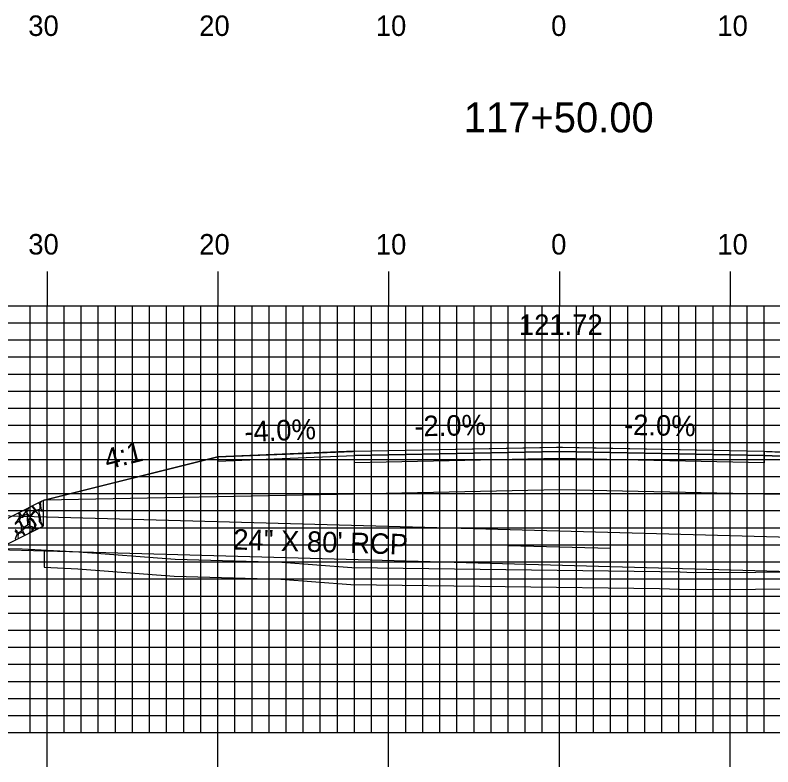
# Model space of a CAD drawing. Extents: x 1771235 to 1771579, y 442591 to 442811.
# Drawn here: x 1771369.2 to 1771413.57, y 442696.66 to 442740.68 of the extents above; entities that cross this region are included whole.
import ezdxf

# ---------------------------------------------------------------- set-up
doc = ezdxf.new("R2010")
doc.units = 0
for name, color, linetype in [('ANNOTATION', 7, 'Continuous'), ('D_Drainage_Culvert', 7, 'Continuous'), ('D_Drainage_Text', 7, 'Continuous'), ('D_Roadway_Centerline', 7, 'Continuous'), ('D_Roadway_Centerline_Text', 7, 'Continuous'), ('D_Roadway_Edge_Shoulder', 7, 'Continuous'), ('D_Roadway_Edge_TW', 7, 'Continuous'), ('D_Roadway_Pavement', 7, 'Continuous'), ('D_Roadway_SlopeLines', 7, 'Continuous'), ('D_Roadway_SubGrade', 7, 'Continuous'), ('GRUBBING IN FILL', 7, 'Continuous'), ('H_V ANNOTATION', 7, 'Continuous'), ('MAJOR', 7, 'Continuous'), ('MINOR', 7, 'Continuous'), ('S_Roadway_Centerline', 7, 'Continuous')]:
    doc.layers.add(name, color=color, linetype=linetype)

msp = doc.modelspace()

# ---------------------------------------------------------------- linework, layer by layer
at = {"layer": 'ANNOTATION'}
msp.add_line((1771365.236, 442709.463), (1771370.82, 442712.255), dxfattribs=at)
at = {"layer": 'D_Drainage_Culvert'}
for p, q in [((1771365.291, 442711.463), (1771445.349, 442709.255)), ((1771398.067, 442709.629), (1771404.067, 442709.463)), ((1771365.236, 442709.463), (1771445.294, 442707.255))]:
    msp.add_line(p, q, dxfattribs=at)
at = {"layer": 'D_Roadway_Centerline'}
msp.add_lwpolyline([(1771370.893, 442712.277), (1771371.045, 442712.315), (1771381.067, 442714.82), (1771388.948, 442715.136), (1771389.067, 442715.14), (1771400.889, 442715.377), (1771401.067, 442715.38), (1771401.246, 442715.377), (1771413.067, 442715.14), (1771413.187, 442715.136), (1771421.067, 442714.82), (1771431.09, 442712.315), (1771431.241, 442712.277), (1771439.262, 442710.272)], dxfattribs=at)
at = {"layer": 'D_Roadway_Edge_Shoulder'}
for points in [[(1771389.067, 442715.14), (1771381.067, 442714.82), (1771381.067, 442714.57), (1771389.067, 442714.89)], [(1771413.067, 442715.14), (1771421.067, 442714.82), (1771421.067, 442714.57), (1771413.067, 442714.89)]]:
    msp.add_lwpolyline(points, close=True, dxfattribs=at)
at = {"layer": 'D_Roadway_Edge_TW'}
msp.add_lwpolyline([(1771389.067, 442714.89), (1771389.067, 442715.14), (1771401.067, 442715.38), (1771413.067, 442715.14), (1771413.067, 442714.89), (1771401.067, 442715.13)], close=True, dxfattribs=at)
at = {"layer": 'D_Roadway_Pavement'}
msp.add_lwpolyline([(1771389.067, 442714.474), (1771389.067, 442714.89), (1771401.067, 442715.13), (1771413.067, 442714.89), (1771413.067, 442714.474), (1771401.067, 442714.714)], close=True, dxfattribs=at)
at = {"layer": 'D_Roadway_SlopeLines'}
for p, q in [((1771370.832, 442712.261), (1771370.832, 442710.761)), ((1771369.982, 442711.822), (1771369.878, 442711.577)), ((1771370.324, 442711.728), (1771370.173, 442711.899)), ((1771370.399, 442711.708), (1771370.208, 442711.95)), ((1771370.574, 442712.132), (1771370.588, 442712.113)), ((1771370.588, 442712.113), (1771370.637, 442712.046)), ((1771370.648, 442712.012), (1771370.649, 442711.78)), ((1771370.7, 442712.027), (1771370.675, 442712.097)), ((1771370.684, 442712.151), (1771370.73, 442712.21)), ((1771370.714, 442711.759), (1771370.703, 442712.011)), ((1771369.468, 442711.359), (1771369.386, 442711.534)), ((1771369.439, 442711.565), (1771369.504, 442711.446)), ((1771369.528, 442711.422), (1771369.602, 442711.385)), ((1771369.673, 442711.402), (1771369.872, 442711.662)), ((1771369.673, 442711.303), (1771369.756, 442711.416)), ((1771369.774, 442711.428), (1771369.848, 442711.439)), ((1771369.866, 442711.738), (1771369.838, 442711.764)), ((1771369.875, 442711.428), (1771369.951, 442711.33)), ((1771369.885, 442711.521), (1771369.987, 442711.382)), ((1771370.075, 442711.378), (1771370.323, 442711.652)), ((1771370.081, 442711.27), (1771370.251, 442711.493)), ((1771370.254, 442711.496), (1771370.358, 442711.592)), ((1771370.436, 442711.592), (1771370.522, 442711.51)), ((1771370.605, 442711.724), (1771370.457, 442711.688)), ((1771370.537, 442711.485), (1771370.606, 442711.26)), ((1771370.579, 442711.601), (1771370.657, 442711.281)), ((1771370.735, 442711.634), (1771370.656, 442711.667)), ((1771370.832, 442711.614), (1771370.746, 442711.631)), ((1771370.832, 442711.672), (1771370.748, 442711.709)), ((1771369.197, 442710.912), (1771369.332, 442711.063)), ((1771369.328, 442710.999), (1771369.197, 442710.848)), ((1771369.339, 442711.074), (1771369.467, 442711.307)), ((1771369.481, 442710.956), (1771369.403, 442711.009)), ((1771369.447, 442711.109), (1771369.507, 442711.244)), ((1771369.529, 442710.974), (1771369.45, 442711.08)), ((1771369.584, 442710.705), (1771369.503, 442710.928)), ((1771369.526, 442711.261), (1771369.657, 442711.293)), ((1771369.584, 442710.836), (1771369.55, 442710.936)), ((1771369.902, 442711.22), (1771369.922, 442710.826)), ((1771369.951, 442711.295), (1771369.908, 442711.239)), ((1771369.951, 442711.108), (1771370.014, 442710.939)), ((1771369.991, 442711.189), (1771369.954, 442711.134)), ((1771370.016, 442710.926), (1771370.006, 442710.825)), ((1771370.173, 442711.102), (1771370.03, 442711.197)), ((1771370.273, 442711.087), (1771370.086, 442711.231)), ((1771370.327, 442710.913), (1771370.18, 442711.096)), ((1771370.425, 442710.842), (1771370.28, 442711.08)), ((1771370.356, 442710.77), (1771370.332, 442710.901)), ((1771370.608, 442711.242), (1771370.602, 442711.041)), ((1771370.614, 442711.005), (1771370.779, 442710.787)), ((1771370.659, 442711.272), (1771370.677, 442711.061)), ((1771370.683, 442711.039), (1771370.83, 442710.76)), ((1771369.197, 442710.554), (1771369.258, 442710.513)), ((1771369.315, 442710.339), (1771369.197, 442710.487)), ((1771369.277, 442710.491), (1771369.315, 442710.415)), ((1771369.389, 442710.388), (1771369.543, 442710.456)), ((1771369.577, 442710.505), (1771369.587, 442710.682)), ((1771369.702, 442710.705), (1771369.622, 442710.778)), ((1771369.66, 442710.43), (1771369.649, 442710.559)), ((1771369.663, 442710.586), (1771369.821, 442710.679)), ((1771369.908, 442710.8), (1771369.735, 442710.701)), ((1771369.827, 442710.682), (1771369.959, 442710.722)), ((1771369.978, 442710.721), (1771370.155, 442710.651)), ((1771370.024, 442710.796), (1771370.262, 442710.705)), ((1771370.173, 442710.623), (1771370.168, 442710.469)), ((1771370.222, 442710.456), (1771370.245, 442710.57)), ((1771370.286, 442710.707), (1771370.342, 442710.74)), ((1771370.288, 442710.614), (1771370.297, 442710.616)), ((1771370.364, 442710.579), (1771370.379, 442710.535)), ((1771370.43, 442710.588), (1771370.378, 442710.723)), ((1771370.381, 442710.75), (1771370.424, 442710.811)), ((1771370.446, 442710.568), (1771370.435, 442710.58)), ((1771370.787, 442710.769), (1771370.796, 442710.743)), ((1771369.197, 442710.028), (1771369.227, 442710.059)), ((1771369.24, 442710.078), (1771369.323, 442710.282)), ((1771369.365, 442710.177), (1771369.421, 442710.322)), ((1771369.396, 442710.044), (1771369.365, 442710.139)), ((1771369.456, 442710.356), (1771369.568, 442710.394)), ((1771369.632, 442710.374), (1771369.748, 442710.22)), ((1771369.776, 442710.234), (1771369.664, 442710.417)), ((1771370.009, 442710.364), (1771370.008, 442710.349)), ((1771370.151, 442710.444), (1771370.026, 442710.389)), ((1771369.226, 442709.968), (1771369.25, 442709.97))]:
    msp.add_line(p, q, dxfattribs=at)
for points in [[(1771381.067, 442714.82), (1771370.832, 442712.261)], [(1771365.236, 442707.963), (1771370.832, 442710.761)]]:
    msp.add_lwpolyline(points, dxfattribs=at)
for centre, radius, start, end in [((1771370.034, 442711.8), 0.057, 124.7904, 156.9778), ((1771370.13, 442711.862), 0.057, 41.2462, 76.5664), ((1771370.592, 442711.779), 0.057, 283.5819, 0.0888), ((1771370.591, 442712.012), 0.057, 0.0888, 36.2192), ((1771370.729, 442712.116), 0.057, 142.3058, 182.6788), ((1771370.729, 442712.116), 0.057, 182.6788, 199.44), ((1771370.646, 442712.008), 0.057, 2.4366, 19.44), ((1771369.334, 442711.509), 0.057, 25.4039, 29.4978), ((1771369.417, 442711.335), 0.057, 331.294, 25.4039), ((1771369.554, 442711.473), 0.057, 208.7575, 243.4931), ((1771369.628, 442711.436), 0.057, 243.4931, 322.6367), ((1771369.779, 442711.399), 0.0285, 98.7462, 143.6864), ((1771369.853, 442711.411), 0.0285, 37.5348, 98.7462), ((1771369.826, 442711.696), 0.057, 322.6367, 46.4321), ((1771369.93, 442711.555), 0.057, 156.9778, 216.6071), ((1771370.033, 442711.416), 0.057, 216.6071, 317.8776), ((1771370.273, 442711.475), 0.0285, 132.7891, 142.5946), ((1771370.281, 442711.69), 0.057, 317.8776, 41.2462), ((1771370.397, 442711.551), 0.057, 46.3639, 132.7891), ((1771370.444, 442711.744), 0.057, 218.373, 283.5819), ((1771370.482, 442711.469), 0.057, 16.8986, 46.3639), ((1771370.634, 442711.614), 0.057, 67.4775, 193.8595), ((1771370.771, 442711.761), 0.057, 182.4366, 246.0375), ((1771370.757, 442711.687), 0.057, 247.4775, 258.7067), ((1771369.371, 442710.961), 0.057, 56.0035, 138.8937), ((1771369.289, 442711.101), 0.057, 318.2412, 331.294), ((1771369.473, 442711.097), 0.0285, 156.1398, 216.7644), ((1771369.449, 442710.909), 0.057, 19.9256, 56.0035), ((1771369.533, 442711.233), 0.0285, 103.7608, 156.1398), ((1771369.415, 442710.889), 0.142, 19.1336, 36.7644), ((1771369.65, 442711.32), 0.0285, 283.7608, 323.6864), ((1771369.93, 442711.221), 0.0285, 142.4314, 182.9903), ((1771369.978, 442711.118), 0.0285, 146.3099, 200.4835), ((1771369.928, 442711.312), 0.0285, 322.4314, 37.5348), ((1771370.015, 442711.174), 0.0285, 56.3099, 146.3099), ((1771369.987, 442710.929), 0.0285, 354.4278, 20.4835), ((1771370.103, 442711.253), 0.0285, 142.5946, 232.5946), ((1771370.157, 442711.079), 0.0285, 38.7742, 56.3099), ((1771370.256, 442711.065), 0.0285, 31.373, 52.5946), ((1771370.304, 442710.896), 0.0285, 10.204, 38.7742), ((1771370.659, 442711.039), 0.057, 178.4306, 216.9888), ((1771370.551, 442711.243), 0.057, 358.4306, 16.8986), ((1771370.602, 442711.267), 0.057, 4.7636, 13.8595), ((1771370.733, 442711.066), 0.057, 184.7636, 207.8015), ((1771369.226, 442710.466), 0.057, 26.5651, 55.7843), ((1771369.52, 442710.508), 0.057, 293.7495, 356.7755), ((1771369.719, 442710.883), 0.142, 199.1336, 227.3215), ((1771369.53, 442710.685), 0.057, 356.7755, 19.9256), ((1771369.678, 442710.562), 0.0285, 120.5102, 184.6669), ((1771369.721, 442710.726), 0.0285, 227.3215, 299.792), ((1771369.836, 442710.655), 0.0285, 106.9275, 120.5102), ((1771369.894, 442710.825), 0.0285, 299.792, 2.9903), ((1771369.968, 442710.695), 0.0285, 68.1986, 106.9275), ((1771370.034, 442710.823), 0.0285, 174.4278, 249.0071), ((1771370.139, 442710.47), 0.0285, 293.7495, 358.1221), ((1771370.145, 442710.624), 0.0285, 358.1221, 68.1986), ((1771370.301, 442710.558), 0.057, 103.134, 168.3664), ((1771370.272, 442710.731), 0.0285, 249.0071, 300.6507), ((1771370.31, 442710.56), 0.057, 19.406, 103.134), ((1771370.328, 442710.765), 0.0285, 300.6507, 10.204), ((1771370.404, 442710.734), 0.0285, 144.4623, 201.1941), ((1771370.401, 442710.827), 0.0285, 324.4623, 31.373), ((1771370.457, 442710.599), 0.0285, 201.1941, 222.2073), ((1771370.733, 442710.752), 0.057, 17.2815, 36.9888), ((1771369.187, 442710.099), 0.057, 315, 337.6938), ((1771369.366, 442710.44), 0.057, 206.5651, 293.7495), ((1771369.271, 442710.303), 0.057, 337.6938, 38.6598), ((1771369.419, 442710.157), 0.057, 159.0265, 198.4349), ((1771369.474, 442710.302), 0.057, 108.7413, 159.0265), ((1771369.586, 442710.34), 0.057, 37.0199, 108.7413), ((1771369.688, 442710.432), 0.0285, 184.6669, 211.5514), ((1771369.702, 442710.186), 0.057, 36.2061, 37.0199), ((1771370.037, 442710.363), 0.0285, 113.7495, 176.6726), ((1771369.231, 442709.911), 0.057, 126.5817, 137.1211), ((1771369.231, 442709.911), 0.057, 95.1944, 126.5817)]:
    msp.add_arc(centre, radius, start, end, dxfattribs=at)
at = {"layer": 'D_Roadway_SubGrade'}
msp.add_lwpolyline([(1771389.067, 442712.64), (1771370.893, 442712.277), (1771381.067, 442714.82), (1771381.067, 442714.57), (1771389.067, 442714.89), (1771401.067, 442715.13), (1771413.067, 442714.89), (1771421.067, 442714.57), (1771421.067, 442714.82), (1771431.241, 442712.277), (1771413.067, 442712.64), (1771401.067, 442712.88)], close=True, dxfattribs=at)
at = {"layer": 'GRUBBING IN FILL'}
msp.add_line((1771370.893, 442709.357), (1771370.893, 442708.355), dxfattribs=at)
msp.add_line((1771370.893, 442709.357), (1771370.893, 442708.355), dxfattribs=at)
msp.add_lwpolyline([(1771370.893, 442708.355), (1771372.866, 442708.25), (1771378.513, 442707.825), (1771384.758, 442707.644), (1771388.863, 442707.337), (1771406.939, 442707.097), (1771408.11, 442707.073), (1771408.898, 442707.041), (1771419.874, 442707.107), (1771429.658, 442706.701), (1771431.241, 442706.635)], dxfattribs=at)
msp.add_lwpolyline([(1771370.893, 442708.355), (1771372.866, 442708.25), (1771378.513, 442707.825), (1771384.758, 442707.644), (1771388.863, 442707.337), (1771406.939, 442707.097), (1771408.11, 442707.073), (1771408.898, 442707.041), (1771419.874, 442707.107), (1771429.658, 442706.701), (1771431.241, 442706.635)], dxfattribs=at)
at = {"layer": 'MAJOR'}
for p, q in [((1771371.067, 442725.669), (1771371.067, 442723.665)), ((1771381.067, 442725.669), (1771381.067, 442723.665)), ((1771391.067, 442725.669), (1771391.067, 442723.665)), ((1771401.067, 442725.669), (1771401.067, 442723.665)), ((1771411.067, 442725.669), (1771411.067, 442723.665)), ((1771261.067, 442723.665), (1771541.067, 442723.665)), ((1771261.067, 442723.665), (1771541.067, 442723.665)), ((1771371.067, 442698.665), (1771371.067, 442723.665)), ((1771381.067, 442698.665), (1771381.067, 442723.665)), ((1771391.067, 442698.665), (1771391.067, 442723.665)), ((1771401.067, 442698.665), (1771401.067, 442723.665)), ((1771411.067, 442698.665), (1771411.067, 442723.665)), ((1771261.067, 442718.665), (1771541.067, 442718.665)), ((1771261.067, 442713.665), (1771541.067, 442713.665)), ((1771261.067, 442708.665), (1771541.067, 442708.665)), ((1771261.067, 442703.665), (1771541.067, 442703.665)), ((1771261.067, 442698.665), (1771541.067, 442698.665)), ((1771261.067, 442698.665), (1771541.067, 442698.665)), ((1771371.067, 442696.661), (1771371.067, 442698.665)), ((1771381.067, 442696.661), (1771381.067, 442698.665)), ((1771391.067, 442696.661), (1771391.067, 442698.665)), ((1771401.067, 442696.661), (1771401.067, 442698.665)), ((1771411.067, 442696.661), (1771411.067, 442698.665))]:
    msp.add_line(p, q, dxfattribs=at)
at = {"layer": 'MINOR'}
for p, q in [((1771370.067, 442698.665), (1771370.067, 442723.665)), ((1771372.067, 442698.665), (1771372.067, 442723.665)), ((1771373.067, 442698.665), (1771373.067, 442723.665)), ((1771374.067, 442698.665), (1771374.067, 442723.665)), ((1771375.067, 442698.665), (1771375.067, 442723.665)), ((1771376.067, 442698.665), (1771376.067, 442723.665)), ((1771377.067, 442698.665), (1771377.067, 442723.665)), ((1771378.067, 442698.665), (1771378.067, 442723.665)), ((1771379.067, 442698.665), (1771379.067, 442723.665)), ((1771380.067, 442698.665), (1771380.067, 442723.665)), ((1771382.067, 442698.665), (1771382.067, 442723.665)), ((1771383.067, 442698.665), (1771383.067, 442723.665)), ((1771384.067, 442698.665), (1771384.067, 442723.665)), ((1771385.067, 442698.665), (1771385.067, 442723.665)), ((1771386.067, 442698.665), (1771386.067, 442723.665)), ((1771387.067, 442698.665), (1771387.067, 442723.665)), ((1771388.067, 442698.665), (1771388.067, 442723.665)), ((1771389.067, 442698.665), (1771389.067, 442723.665)), ((1771390.067, 442698.665), (1771390.067, 442723.665)), ((1771392.067, 442698.665), (1771392.067, 442723.665)), ((1771393.067, 442698.665), (1771393.067, 442723.665)), ((1771394.067, 442698.665), (1771394.067, 442723.665)), ((1771395.067, 442698.665), (1771395.067, 442723.665)), ((1771396.067, 442698.665), (1771396.067, 442723.665)), ((1771397.067, 442698.665), (1771397.067, 442723.665)), ((1771398.067, 442698.665), (1771398.067, 442723.665)), ((1771399.067, 442698.665), (1771399.067, 442723.665)), ((1771400.067, 442698.665), (1771400.067, 442723.665)), ((1771402.067, 442698.665), (1771402.067, 442723.665)), ((1771403.067, 442698.665), (1771403.067, 442723.665)), ((1771404.067, 442698.665), (1771404.067, 442723.665)), ((1771405.067, 442698.665), (1771405.067, 442723.665)), ((1771406.067, 442698.665), (1771406.067, 442723.665)), ((1771407.067, 442698.665), (1771407.067, 442723.665)), ((1771408.067, 442698.665), (1771408.067, 442723.665)), ((1771409.067, 442698.665), (1771409.067, 442723.665)), ((1771410.067, 442698.665), (1771410.067, 442723.665)), ((1771412.067, 442698.665), (1771412.067, 442723.665)), ((1771413.067, 442698.665), (1771413.067, 442723.665)), ((1771261.067, 442722.665), (1771541.067, 442722.665)), ((1771261.067, 442721.665), (1771541.067, 442721.665)), ((1771261.067, 442720.665), (1771541.067, 442720.665)), ((1771261.067, 442719.665), (1771541.067, 442719.665)), ((1771261.067, 442717.665), (1771541.067, 442717.665)), ((1771261.067, 442716.665), (1771541.067, 442716.665)), ((1771261.067, 442715.665), (1771541.067, 442715.665)), ((1771261.067, 442714.665), (1771541.067, 442714.665)), ((1771261.067, 442712.665), (1771541.067, 442712.665)), ((1771261.067, 442711.665), (1771541.067, 442711.665)), ((1771261.067, 442710.665), (1771541.067, 442710.665)), ((1771261.067, 442709.665), (1771541.067, 442709.665)), ((1771261.067, 442707.665), (1771541.067, 442707.665)), ((1771261.067, 442706.665), (1771541.067, 442706.665)), ((1771261.067, 442705.665), (1771541.067, 442705.665)), ((1771261.067, 442704.665), (1771541.067, 442704.665)), ((1771261.067, 442702.665), (1771541.067, 442702.665)), ((1771261.067, 442701.665), (1771541.067, 442701.665)), ((1771261.067, 442700.665), (1771541.067, 442700.665)), ((1771261.067, 442699.665), (1771541.067, 442699.665))]:
    msp.add_line(p, q, dxfattribs=at)
at = {"layer": 'S_Roadway_Centerline'}
msp.add_lwpolyline([(1771328.588, 442710.405), (1771346.503, 442709.868), (1771348.907, 442709.803), (1771349.353, 442709.787), (1771349.877, 442709.796), (1771369.609, 442709.425), (1771372.93, 442709.248), (1771378.565, 442708.824), (1771384.81, 442708.643), (1771388.907, 442708.337), (1771406.956, 442708.096), (1771408.14, 442708.073), (1771408.915, 442708.041), (1771419.892, 442708.107), (1771429.7, 442707.701), (1771432.066, 442707.602), (1771435.861, 442707.523), (1771443.742, 442707.524), (1771448.815, 442707.162), (1771463.73, 442706.723)], dxfattribs=at)

# ---------------------------------------------------------------- texts
at = {"layer": 'ANNOTATION'}
for s, rotation, p in [('-2.0%', 1.1458, (1771392.584, 442716.011)), ('-2.0%', 358.8542, (1771404.843, 442716.105)), ('-4.0%', 2.2906, (1771382.64, 442715.685)), ('4:1', 14.0362, (1771374.592, 442714.063))]:
    msp.add_text(s, height=1.2, rotation=rotation, dxfattribs=at).set_placement(p)
at = {"layer": 'D_Drainage_Text'}
msp.add_text('24" X 80\' RCP', height=1.2, rotation=358.3041, dxfattribs=at).set_placement((1771381.952, 442709.391))
at = {"layer": 'D_Roadway_Centerline_Text'}
msp.add_text('121.72', height=1.2, dxfattribs=at).set_placement((1771398.698, 442721.958))
at = {"layer": 'H_V ANNOTATION'}
for s, height, p in [('30', 1.2, (1771369.965, 442739.465)), ('20', 1.2, (1771379.975, 442739.465)), ('10', 1.2, (1771390.318, 442739.465)), ('0', 1.2, (1771400.585, 442739.465)), ('10', 1.2, (1771410.318, 442739.465)), ('117+50.00', 1.75, (1771395.465, 442733.821)), ('30', 1.2, (1771369.965, 442726.665)), ('20', 1.2, (1771379.975, 442726.665)), ('10', 1.2, (1771390.318, 442726.665)), ('0', 1.2, (1771400.585, 442726.665)), ('10', 1.2, (1771410.318, 442726.665))]:
    msp.add_text(s, height=height, dxfattribs=at).set_placement(p)

doc.saveas('drawing.dxf')
